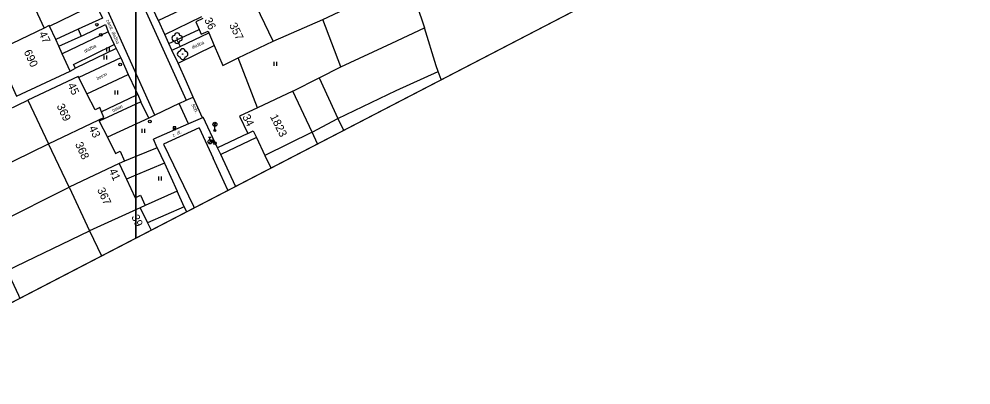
# Model space of a CAD drawing. Extents: x -493753 to -49290, y -1127285 to -112654.
# Drawn here: x -493146.9 to -492968.4, y -1127096.9 to -1127028.4 of the extents above; entities that cross this region are included whole.
import ezdxf

# ---------------------------------------------------------------- set-up
doc = ezdxf.new("R2010")
doc.units = 0
for name, color, linetype in [('Vrstva 1', 7, 'Continuous'), ('Vrstva 10', 7, 'Continuous'), ('Vrstva 11', 7, 'Continuous'), ('Vrstva 22', 7, 'Continuous'), ('Vrstva 27', 7, 'Continuous'), ('Vrstva 28', 7, 'Continuous'), ('Vrstva 33', 7, 'Continuous'), ('Vrstva 36', 7, 'Continuous'), ('Vrstva 40', 7, 'Continuous'), ('Vrstva 42', 7, 'Continuous'), ('Vrstva 43', 7, 'Continuous'), ('Vrstva 44', 7, 'Continuous'), ('Vrstva 5', 7, 'Continuous'), ('Vrstva 60', 7, 'Continuous'), ('Vrstva 7', 7, 'Continuous')]:
    doc.layers.add(name, color=color, linetype=linetype)

msp = doc.modelspace()

# ---------------------------------------------------------------- linework, layer by layer
at = {"layer": 'Vrstva 1'}
msp.add_lwpolyline([(-493753.129, -1126773.634), (-493540.881, -1127284.865), (-492737.61, -1126868.64), (-492950.39, -1126535.73)], dxfattribs=at)
at = {"layer": 'Vrstva 10'}
for p, q in [((-493121.43, -1127046.36), (-493137.02, -1127011.69)), ((-493125, -1127022.81), (-493115.54, -1127043.53)), ((-493113.81, -1127025.41), (-493120.74, -1127028.66)), ((-493119.56, -1127031.27), (-493112.64, -1127027.86)), ((-493128.67, -1127033.91), (-493136.28, -1127037.55)), ((-493112.48, -1127046.86), (-493114.26, -1127043)), ((-493122.57, -1127046.9), (-493124.07, -1127043.88)), ((-493116.89, -1127044.21), (-493121.43, -1127046.36)), ((-493116.89, -1127044.21), (-493115.54, -1127043.53)), ((-493115.11, -1127047.99), (-493116.89, -1127044.21)), ((-493121.43, -1127046.36), (-493122.57, -1127046.9)), ((-493112.34, -1127046.77), (-493112.48, -1127046.86)), ((-493115.11, -1127047.99), (-493121.65, -1127050.88)), ((-493113.14, -1127048.75), (-493119.8, -1127051.79)), ((-493113.14, -1127048.75), (-493110.49, -1127054.41)), ((-493119.8, -1127051.79), (-493114.18, -1127063.39)), ((-493119.62, -1127055.37), (-493117.26, -1127060.61)), ((-493115.93, -1127063.53), (-493122.81, -1127066.51)), ((-493115.93, -1127063.53), (-493115.51, -1127064.45)), ((-493115.51, -1127064.45), (-493115.509, -1127064.453)), ((-493114.18, -1127063.39), (-493114.036, -1127063.69))]:
    msp.add_line(p, q, dxfattribs=at)
for points in [[(-493141.18, -1127029.68), (-493132.54, -1127025.54), (-493131.24, -1127028.23), (-493135.8, -1127030.24)], [(-493120.74, -1127028.66), (-493120.97, -1127028.17), (-493121.5, -1127027.05)], [(-493119.56, -1127031.27), (-493120.74, -1127028.66)], [(-493135.8, -1127030.24), (-493140.01, -1127032.21)], [(-493139.43, -1127033.47), (-493135.21, -1127031.56), (-493134.94, -1127031.44), (-493130.69, -1127029.41), (-493130.16, -1127030.76)], [(-493117.3, -1127032.24), (-493113.1, -1127030.32)], [(-493130.16, -1127030.76), (-493138.77, -1127034.89)], [(-493130.16, -1127030.76), (-493129.04, -1127033.16)], [(-493118.79, -1127032.93), (-493119.56, -1127031.27)], [(-493118.79, -1127032.93), (-493117.3, -1127032.24)], [(-493118.21, -1127034.2), (-493116.7, -1127033.48), (-493111.31, -1127030.92)], [(-493117.3, -1127032.24), (-493116.7, -1127033.48)], [(-493136.28, -1127037.55), (-493136.67, -1127036.89), (-493129.04, -1127033.16), (-493128.67, -1127033.91), (-493127.8, -1127035.66)], [(-493118.21, -1127034.2), (-493118.79, -1127032.93)], [(-493114.26, -1127043), (-493115.46, -1127040.15), (-493117.07, -1127036.65), (-493118.21, -1127034.2)], [(-493117.07, -1127036.65), (-493110.27, -1127033.34)], [(-493127.8, -1127035.66), (-493135.69, -1127039.34)], [(-493127.8, -1127035.66), (-493126.45, -1127038.72)], [(-493137.27, -1127038.13), (-493136.28, -1127037.55)], [(-493134.14, -1127042.38), (-493126.45, -1127038.72), (-493125, -1127041.72)], [(-493125, -1127042.69), (-493131.4, -1127045.75)], [(-493125, -1127041.72), (-493124.62, -1127042.51)], [(-493124.62, -1127042.51), (-493124.07, -1127043.88), (-493125, -1127044.31)], [(-493124.62, -1127042.51), (-493125, -1127042.69)], [(-493125, -1127044.31), (-493131.84, -1127047.49)], [(-493104.01, -1127049.81), (-493109.66, -1127052.46), (-493112.34, -1127046.77)], [(-493122.57, -1127046.9), (-493130.32, -1127050.51)], [(-493120.99, -1127052.47), (-493121.65, -1127050.88)], [(-493120.99, -1127052.47), (-493125, -1127054.11)], [(-493125, -1127054.11), (-493127.1, -1127054.97)], [(-493119.62, -1127055.37), (-493125, -1127057.61)], [(-493107.714, -1127060.414), (-493110.49, -1127054.41)], [(-493125, -1127057.61), (-493126.75, -1127058.34)], [(-493117.26, -1127060.61), (-493123.21, -1127063.29)]]:
    msp.add_lwpolyline(points, dxfattribs=at)
at = {"layer": 'Vrstva 11'}
for p, q in [((-493115.54, -1127043.53), (-493114.26, -1127043)), ((-493113.79, -1127047.44), (-493115.11, -1127047.99)), ((-493112.48, -1127046.86), (-493113.79, -1127047.44)), ((-493115.93, -1127063.53), (-493117.26, -1127060.61))]:
    msp.add_line(p, q, dxfattribs=at)
for points in [[(-493089.9, -1127028.48), (-493076.5, -1127022.08)], [(-493072.39, -1127025.58), (-493070.89, -1127029.99)], [(-493099.23, -1127032.5), (-493089.9, -1127028.48)], [(-493086.58, -1127037.33), (-493089.9, -1127028.48)], [(-493135.8, -1127030.24), (-493135.21, -1127031.56)], [(-493077.02, -1127032.87), (-493070.89, -1127029.99)], [(-493068.68, -1127037.15), (-493070.89, -1127029.99)], [(-493086.58, -1127037.33), (-493077.02, -1127032.87)], [(-493102.19, -1127044.99), (-493105.79, -1127035.66)], [(-493090.61, -1127039.35), (-493086.58, -1127037.33)], [(-493068.29, -1127038.21), (-493068.68, -1127037.15)], [(-493095.58, -1127041.87), (-493090.61, -1127039.35)], [(-493090.61, -1127039.35), (-493087.1, -1127047.01)], [(-493076.17, -1127041.72), (-493068.29, -1127038.21)], [(-493067.756, -1127039.71), (-493068.29, -1127038.21)], [(-493087.1, -1127047.01), (-493076.17, -1127041.72)], [(-493091.95, -1127049.56), (-493087.1, -1127047.01)], [(-493087.1, -1127047.01), (-493086.071, -1127049.2)], [(-493102.39, -1127050.57), (-493109.07, -1127053.73)], [(-493120.99, -1127052.47), (-493119.62, -1127055.37)], [(-493106.283, -1127059.672), (-493109.07, -1127053.73), (-493109.66, -1127052.46)]]:
    msp.add_lwpolyline(points, dxfattribs=at)
at = {"layer": 'Vrstva 22'}
for centre in [(-493117.24, -1127031.94), (-493116.21, -1127034.93)]:
    msp.add_circle(centre, 0.05, dxfattribs=at)
for centre, start, end in [((-493117.74, -1127031.94), 90, 270), ((-493117.24, -1127031.44), 360, 180), ((-493117.24, -1127032.44), 180, 0), ((-493116.74, -1127031.94), 270, 90), ((-493116.21, -1127034.43), 360, 180), ((-493116.71, -1127034.93), 90, 270), ((-493116.21, -1127035.43), 180, 0), ((-493115.71, -1127034.93), 270, 90)]:
    msp.add_arc(centre, 0.5, start, end, dxfattribs=at)
at = {"layer": 'Vrstva 27'}
msp.add_line((-493118, -1127048.83), (-493117.5, -1127048.83), dxfattribs=at)
msp.add_lwpolyline([(-493118, -1127049.08), (-493117.5, -1127049.08), (-493117.5, -1127048.58), (-493118, -1127048.58)], close=True, dxfattribs=at)
at = {"layer": 'Vrstva 28'}
for p, q in [((-493111.345, -1127051.625), (-493110.815, -1127051.095)), ((-493111.33, -1127050.46), (-493110.83, -1127050.46)), ((-493111.08, -1127050.985), (-493111.08, -1127050.46))]:
    msp.add_line(p, q, dxfattribs=at)
for centre, radius in [((-493132.27, -1127029.42), 0.25), ((-493131.57, -1127031.33), 0.25), ((-493127.94, -1127036.89), 0.25), ((-493122.35, -1127047.57), 0.25), ((-493111.08, -1127051.36), 0.375), ((-493110.72, -1127051.23), 0.25), ((-493110.15, -1127051.61), 0.25)]:
    msp.add_circle(centre, radius, dxfattribs=at)
at = {"layer": 'Vrstva 33'}
for p, q in [((-493110.425, -1127047.815), (-493109.895, -1127048.345)), ((-493110.425, -1127048.345), (-493109.895, -1127047.815)), ((-493110.16, -1127049.23), (-493110.16, -1127048.455))]:
    msp.add_line(p, q, dxfattribs=at)
for centre, radius in [((-493110.16, -1127048.08), 0.375), ((-493110.16, -1127049.23), 0.19), ((-493110.16, -1127049.23), 0.05)]:
    msp.add_circle(centre, radius, dxfattribs=at)
at = {"layer": 'Vrstva 36'}
for p, q in [((-493130.45, -1127034.42), (-493130.45, -1127033.67)), ((-493129.95, -1127034.42), (-493129.95, -1127033.67)), ((-493130.91, -1127035.93), (-493130.91, -1127035.18)), ((-493130.41, -1127035.93), (-493130.41, -1127035.18)), ((-493099.02, -1127037.1), (-493099.02, -1127036.35)), ((-493098.52, -1127037.1), (-493098.52, -1127036.35)), ((-493128.83, -1127042.48), (-493128.83, -1127041.73)), ((-493128.33, -1127042.48), (-493128.33, -1127041.73)), ((-493123.79, -1127049.66), (-493123.79, -1127048.91)), ((-493123.29, -1127049.66), (-493123.29, -1127048.91)), ((-493120.69, -1127058.63), (-493120.69, -1127057.88)), ((-493120.19, -1127058.63), (-493120.19, -1127057.88))]:
    msp.add_line(p, q, dxfattribs=at)
at = {"layer": 'Vrstva 5'}
for p, q in [((-493105.53, -1127046.56), (-493104.01, -1127049.81)), ((-493104.01, -1127049.81), (-493102.98, -1127049.33)), ((-493125, -1127061.76), (-493124.11, -1127061.35)), ((-493124.11, -1127061.35), (-493123.21, -1127063.29)), ((-493123.21, -1127063.29), (-493124.18, -1127063.73))]:
    msp.add_line(p, q, dxfattribs=at)
for points in [[(-493146.91, -1127022.39), (-493146.01, -1127021.96), (-493145.97, -1127022.06), (-493144.75, -1127024.62), (-493144.16, -1127025.85), (-493143.43, -1127027.38), (-493142.15, -1127030.07)], [(-493099.23, -1127032.5), (-493103.18, -1127024.29)], [(-493112.45, -1127028.26), (-493113.72, -1127028.86)], [(-493113.72, -1127028.86), (-493113.1, -1127030.32), (-493112.72, -1127031.2), (-493111.43, -1127030.65), (-493111.31, -1127030.92), (-493110.27, -1127033.34), (-493108.68, -1127037.05)], [(-493151.23, -1127034.4), (-493147.34, -1127042.8), (-493137.27, -1127038.13), (-493138.77, -1127034.89), (-493139.43, -1127033.47), (-493140.01, -1127032.21), (-493141.18, -1127029.68), (-493141.22, -1127029.6), (-493142.15, -1127030.07)], [(-493142.15, -1127030.07), (-493151.23, -1127034.4)], [(-493105.79, -1127035.66), (-493099.23, -1127032.5)], [(-493108.68, -1127037.05), (-493105.79, -1127035.66)], [(-493131.95, -1127047.27), (-493130.96, -1127046.8), (-493131.4, -1127045.75), (-493131.75, -1127044.92), (-493132.62, -1127045.36), (-493134.14, -1127042.38), (-493135.69, -1127039.34), (-493135.8, -1127039.11), (-493145.21, -1127043.55), (-493141.35, -1127051.71)], [(-493095.58, -1127041.87), (-493102.19, -1127044.99)], [(-493091.95, -1127049.56), (-493095.58, -1127041.87)], [(-493102.19, -1127044.99), (-493105.53, -1127046.56)], [(-493141.35, -1127051.71), (-493131.95, -1127047.27)], [(-493131.95, -1127047.27), (-493131.84, -1127047.49), (-493130.32, -1127050.51), (-493128.8, -1127053.53), (-493127.89, -1127053.09), (-493127.1, -1127054.97)], [(-493102.98, -1127049.33), (-493102.39, -1127050.57), (-493100.79, -1127053.95)], [(-493091.95, -1127049.56), (-493100.79, -1127053.95)], [(-493090.931, -1127051.718), (-493091.95, -1127049.56)], [(-493137.5, -1127059.87), (-493141.35, -1127051.71)], [(-493128.1, -1127055.44), (-493137.5, -1127059.87)], [(-493127.1, -1127054.97), (-493128.1, -1127055.44)], [(-493128.1, -1127055.44), (-493126.75, -1127058.34), (-493125.13, -1127061.82), (-493125, -1127061.76)], [(-493100.79, -1127053.95), (-493099.696, -1127056.26)], [(-493137.5, -1127059.87), (-493133.65, -1127068.04)], [(-493124.18, -1127063.73), (-493133.65, -1127068.04)], [(-493124.18, -1127063.73), (-493122.81, -1127066.51), (-493122.131, -1127067.885)], [(-493133.65, -1127068.04), (-493131.441, -1127072.709)]]:
    msp.add_lwpolyline(points, dxfattribs=at)
at = {"layer": 'Vrstva 60'}
msp.add_line((-493125, -1127069.371), (-492991.121, -1127000), dxfattribs=at)
for points in [[(-493659.148, -1127000), (-493540.881, -1127284.865), (-493125, -1127069.371)], [(-493125, -1127069.371), (-493125, -1127000), (-493659.148, -1127000)], [(-492991.121, -1127000), (-493125, -1127000), (-493125, -1127069.371)]]:
    msp.add_lwpolyline(points, dxfattribs=at)
at = {"layer": 'Vrstva 7'}
for p, q in [((-493160.63, -1127050.95), (-493145.21, -1127043.55)), ((-493156.73, -1127059.26), (-493141.35, -1127051.71)), ((-493152.8, -1127067.49), (-493137.5, -1127059.87)), ((-493149.13, -1127075.46), (-493133.65, -1127068.04))]:
    msp.add_line(p, q, dxfattribs=at)
msp.add_lwpolyline([(-493146.717, -1127080.624), (-493146.93, -1127080.17), (-493149.13, -1127075.46), (-493150.58, -1127072.32), (-493152.8, -1127067.49)], dxfattribs=at)

# ---------------------------------------------------------------- texts
at = {"layer": 'Vrstva 40'}
for s, rotation, p in [('zámk. dlažba', 294.21194, (-493130.555, -1127028.621)), ('dlažba', 26.91337, (-493134.522, -1127034.7)), ('dlažba', 24.49046, (-493114.368, -1127033.985)), ('beton', 26.91337, (-493132.173, -1127039.79)), ('beton', 26.91337, (-493129.243, -1127045.83)), ('z. dl.', 24.53463, (-493117.949, -1127050.431))]:
    msp.add_text(s, height=0.6, rotation=rotation, dxfattribs=at).set_placement(p)
at = {"layer": 'Vrstva 42'}
msp.add_text('sch.', height=0.75, rotation=295.21572, dxfattribs=at).set_placement((-493114.598, -1127044.401))
at = {"layer": 'Vrstva 43'}
for s, rotation, p in [('357', 295.7329, (-493107.517, -1127029.477)), ('690', 294.85661, (-493146.02, -1127034.499)), ('369', 295.25918, (-493139.862, -1127044.634)), ('1823', 296.38849, (-493099.86, -1127046.62)), ('368', 294.45581, (-493136.397, -1127051.781)), ('367', 294.45626, (-493132.269, -1127060.315))]:
    msp.add_text(s, height=1.5, rotation=rotation, dxfattribs=at).set_placement(p)
at = {"layer": 'Vrstva 44'}
for s, rotation, p in [('36', 295.7329, (-493112.194, -1127028.52)), ('47', 294.85661, (-493143.214, -1127031.072)), ('45', 295.25918, (-493137.817, -1127040.726)), ('34', 296.38849, (-493105.054, -1127046.65)), ('43', 294.45581, (-493133.826, -1127048.739)), ('41', 294.45626, (-493130.061, -1127056.765)), ('39', 294.53468, (-493125.857, -1127065.385))]:
    msp.add_text(s, height=1.5, rotation=rotation, dxfattribs=at).set_placement(p)

doc.saveas('drawing.dxf')
